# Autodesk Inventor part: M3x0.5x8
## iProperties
Company: 한국ATC센터
Created: 2009-02
Part Number: M3x0.5x8
Document SubType Name: Modeling
Designer: KYOUNG IL JANG
Density: 2.71 g/cm^3
Mass: 199.244 g
Surface Area: 195.422 cm^2
Volume: 73.522 cm^3
Material: 알루미늄-6061
Vendor: CBT Solutions
Author: KYOUNG IL JANG
